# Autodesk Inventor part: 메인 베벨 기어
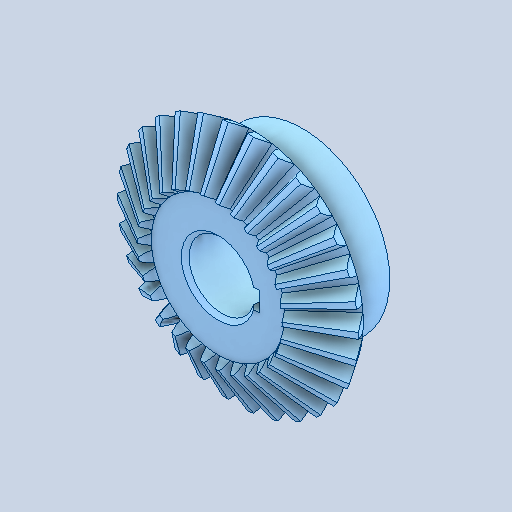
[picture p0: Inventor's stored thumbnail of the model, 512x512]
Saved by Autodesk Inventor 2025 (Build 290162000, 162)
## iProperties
Created: 2026-07
Part Number: 메인 베벨 기어
Material: 강철, 합금
Document SubType Name: Modeling
Designer: KDI
Density: 7.73 g/cm^3
Appearance: 기본값
Author: jhkim
Revision Number: 1
Sending System: Autodesk Inventor 2027
Preprocessor: ST-DEVELOPER v20.1
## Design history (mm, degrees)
feature "Solid1"
node "솔리드1"
